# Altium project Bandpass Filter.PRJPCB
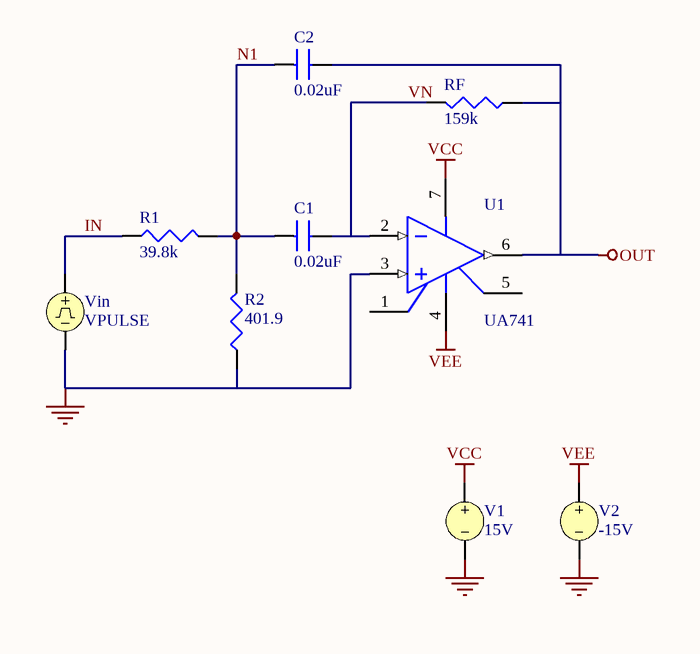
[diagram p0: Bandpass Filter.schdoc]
1 sheet, 9 parts. Net scope: global (net labels, ports and power ports of the same name join across sheets).

## Sheet Bandpass Filter.schdoc: Bandpass Filter
size A4; Organization: Altium Limited; Address1: L3, 12a Rodborough Rd; Address2: Frenchs Forest; Address3: NSW; Address4: Australia 2086; DocumentNumber: 1; SheetNumber: 1; SheetTotal: 1

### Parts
C1  0.02uF
C2  0.02uF
R1  39.8k
R2  401.9
RF  159k
U1  UA741
V1  15V
V2  -15V
Vin  VPULSE

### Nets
GND: R2.2(BOT) U1.3(+IN) V1.2 V2.2 Vin.2
OUT: C2.2 RF.2(BOT) U1.6(OUT)
VCC: U1.7(V+) V1.1
VEE: U1.4(V-) V2.1
IN: R1.2(BOT) Vin.1
N1: C1.1 C2.1 R1.1(TOP) R2.1(TOP)
VN: C1.2 RF.1(TOP) U1.2(-IN)

Not connected (* = marked no-connect by the designer): U1 1(OFFSET_NULL_1) 5(OFFSET_NULL_2)

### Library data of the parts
C1 C2 = CAP: Capacitor
R1 R2 RF = RES: Resistor
U1 = UA741: General-Purpose Operational Amplifier
V1 V2 = VSRC: Voltage Source
Vin = VPULSE: Pulse Voltage Source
